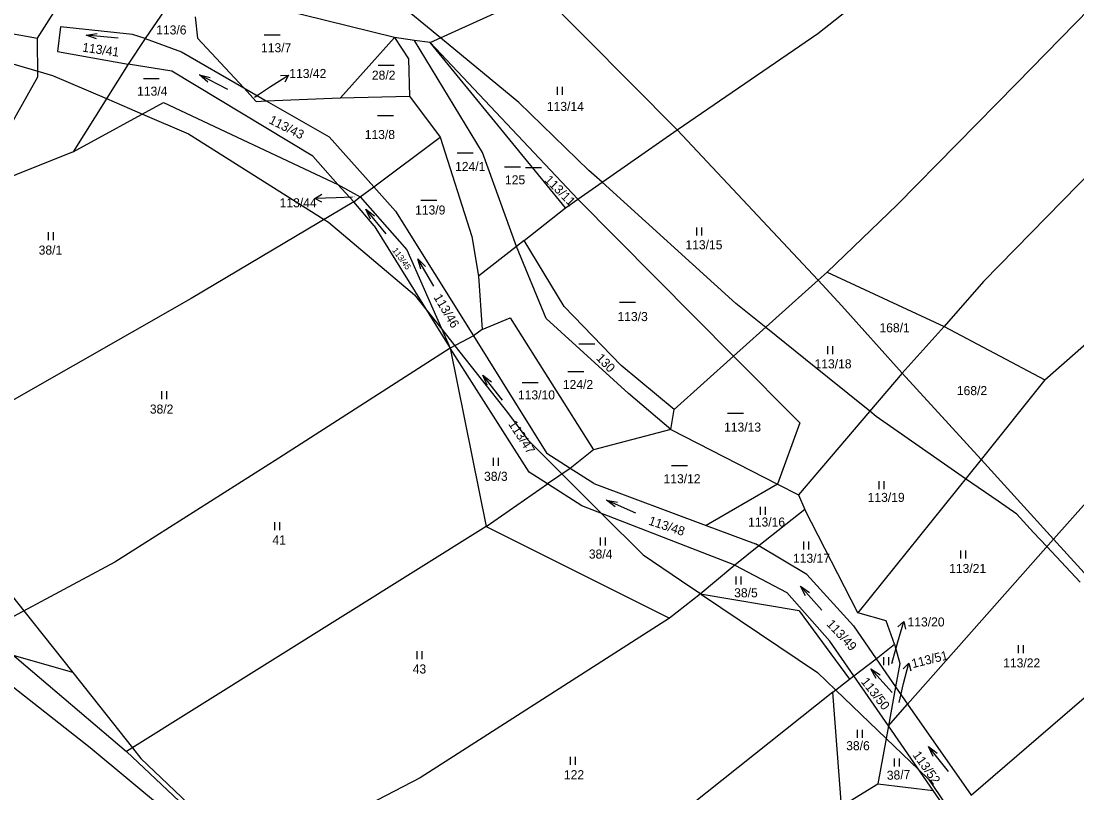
# Model space of a CAD drawing. Extents: x -749173 to -746119, y -1132678 to -1130338.
# Drawn here: x -747690.2 to -747491.9, y -1131005.9 to -1130860.8 of the extents above; entities that cross this region are included whole.
import ezdxf

# ---------------------------------------------------------------- set-up
doc = ezdxf.new("R2010")
doc.units = 0
for name, color, linetype in [('Vrstva 1', 7, 'Continuous'), ('Vrstva 16', 7, 'Continuous'), ('Vrstva 18', 7, 'Continuous'), ('Vrstva 25', 7, 'Continuous'), ('Vrstva 52', 7, 'Continuous'), ('Vrstva 6', 7, 'Continuous')]:
    doc.layers.add(name, color=color, linetype=linetype)

msp = doc.modelspace()

# ---------------------------------------------------------------- linework, layer by layer
at = {"layer": 'Vrstva 1'}
for points in [[(-747687.14, -1130864.03), (-747678.53, -1130850.34)], [(-747592.89, -1130855.02), (-747566.95, -1130881.22)], [(-747662, -1130856.84), (-747666.96, -1130864.06)], [(-747620.11, -1130863.87), (-747650.32, -1130856.36)], [(-747613.42, -1130864.85), (-747598.03, -1130857.85)], [(-747704.65, -1130860.86), (-747687.14, -1130864.03)], [(-747682.82, -1130861.87), (-747683.44, -1130866.5)], [(-747669.33, -1130863.29), (-747682.82, -1130861.87)], [(-747687.11, -1130871.26), (-747687.14, -1130864.03)], [(-747666.96, -1130864.06), (-747669.33, -1130863.29)], [(-747616.32, -1130864.44), (-747620.11, -1130863.87)], [(-747666.96, -1130864.06), (-747660.13, -1130866.55)], [(-747613.42, -1130864.85), (-747616.32, -1130864.44)], [(-747613.42, -1130864.85), (-747585.62, -1130894.26)], [(-747683.44, -1130866.5), (-747670.15, -1130868.87)], [(-747660.13, -1130866.55), (-747648.43, -1130873.34)], [(-747670.15, -1130868.87), (-747680.49, -1130885.34)], [(-747661.9, -1130870.18), (-747670.15, -1130868.87)], [(-747693.1, -1130881.99), (-747687.11, -1130871.26)], [(-747635.43, -1130886.18), (-747661.9, -1130870.18)], [(-747648.43, -1130873.34), (-747644.19, -1130875.8)], [(-747644.19, -1130875.8), (-747632.37, -1130882.58)], [(-747680.49, -1130885.34), (-747663.47, -1130876.12)], [(-747663.47, -1130876.12), (-747630.73, -1130891.53)], [(-747566.95, -1130881.22), (-747540.5, -1130909.52)], [(-747624, -1130891.96), (-747632.37, -1130882.58)], [(-747680.49, -1130885.34), (-747734.07, -1130906.85)], [(-747630.73, -1130891.53), (-747635.43, -1130886.18)], [(-747627.71, -1130894.75), (-747630.73, -1130891.53)], [(-747619.89, -1130896.55), (-747624, -1130891.96)], [(-747623.92, -1130899.27), (-747627.71, -1130894.75)], [(-747585.62, -1130894.26), (-747556.37, -1130923.79)], [(-747619.89, -1130896.55), (-747605.27, -1130919.98)], [(-747623.92, -1130899.27), (-747609.63, -1130922.29)], [(-747540.5, -1130909.52), (-747536.03, -1130914.31)], [(-747536.03, -1130914.31), (-747524.7, -1130926.96)], [(-747605.27, -1130919.98), (-747591.5, -1130942.05)], [(-747594.77, -1130945.6), (-747609.63, -1130922.29)], [(-747556.37, -1130923.79), (-747543.96, -1130936.32)], [(-747524.7, -1130926.96), (-747509.89, -1130943.21)], [(-747543.96, -1130936.32), (-747548.12, -1130947.84)], [(-747587.06, -1130944.87), (-747591.5, -1130942.05)], [(-747509.89, -1130943.21), (-747496.26, -1130958.17)], [(-747582.62, -1130947.7), (-747587.06, -1130944.87)], [(-747591.34, -1130947.8), (-747594.77, -1130945.6)], [(-747584.92, -1130951.93), (-747591.34, -1130947.8)], [(-747582.62, -1130947.7), (-747561.51, -1130955.61)], [(-747548.12, -1130947.84), (-747561.51, -1130955.61)], [(-747556.12, -1130963.07), (-747584.92, -1130951.93)], [(-747561.51, -1130955.61), (-747552.29, -1130959.07)], [(-747551.66, -1130959.44), (-747552.29, -1130959.07)], [(-747496.26, -1130958.17), (-747480.85, -1130975.08)], [(-747542.61, -1130964.81), (-747551.66, -1130959.44)], [(-747556.12, -1130963.07), (-747546.35, -1130968.19)], [(-747542.61, -1130964.81), (-747533.86, -1130974.48)], [(-747538.28, -1130977.32), (-747546.35, -1130968.19)], [(-747533.86, -1130974.48), (-747529.57, -1130980.67)], [(-747696.99, -1130975.53), (-747670.43, -1130998.05)], [(-747533.76, -1130983.87), (-747538.28, -1130977.32)], [(-747677.24, -1130997.39), (-747699.35, -1130980.06)], [(-747529.57, -1130980.67), (-747525.94, -1130985.9)], [(-747527.29, -1130993.25), (-747533.76, -1130983.87)], [(-747525.94, -1130985.9), (-747523.68, -1130989.16)], [(-747523.68, -1130989.16), (-747511.77, -1131006.31)], [(-747518.9, -1131005.41), (-747527.29, -1130993.25)], [(-747641.15, -1131027.46), (-747677.24, -1130997.39)], [(-747670.43, -1130998.05), (-747647.48, -1131019.78)], [(-747515.79, -1131009.83), (-747518.9, -1131005.41)]]:
    msp.add_lwpolyline(points, dxfattribs=at)
at = {"layer": 'Vrstva 16'}
for p, q in [((-747641.51, -1130871.02), (-747640.01, -1130870.94)), ((-747633.73, -1130894.84), (-747635.05, -1130894.14)), ((-747525.5, -1130974.67), (-747524.42, -1130973.62)), ((-747524.51, -1130982.53), (-747523.47, -1130981.45))]:
    msp.add_line(p, q, dxfattribs=at)
for points in [[(-747643.37, -1130873.12), (-747640.01, -1130870.94), (-747640.7, -1130872.28)], [(-747646.42, -1130875.1), (-747643.37, -1130873.12)], [(-747631.05, -1130894.01), (-747635.05, -1130894.14), (-747633.77, -1130893.34)], [(-747627.99, -1130893.91), (-747631.05, -1130894.01)], [(-747525.51, -1130977.47), (-747524.42, -1130973.62), (-747524.05, -1130975.08)], [(-747526.65, -1130981.51), (-747525.51, -1130977.47)], [(-747524.43, -1130985.33), (-747523.47, -1130981.45), (-747523.05, -1130982.89)], [(-747525.3, -1130988.86), (-747524.43, -1130985.33)]]:
    msp.add_lwpolyline(points, dxfattribs=at)
at = {"layer": 'Vrstva 25'}
for p, q in [((-747672.03, -1130864.03), (-747678.01, -1130863.43)), ((-747644.55, -1130863.36), (-747641.55, -1130863.36)), ((-747623.17, -1130869.11), (-747620.17, -1130869.11)), ((-747667.28, -1130871.61), (-747664.28, -1130871.61)), ((-747651.39, -1130873.64), (-747656.73, -1130870.92)), ((-747589.55, -1130873.13), (-747589.55, -1130874.63)), ((-747588.55, -1130874.63), (-747588.55, -1130873.13)), ((-747623.28, -1130878.56), (-747620.28, -1130878.56)), ((-747608.3, -1130885.57), (-747605.3, -1130885.57)), ((-747599.42, -1130888.17), (-747596.42, -1130888.17)), ((-747595.5, -1130888.31), (-747592.5, -1130888.31)), ((-747615.13, -1130894.45), (-747612.13, -1130894.45)), ((-747621.66, -1130900.78), (-747625.5, -1130896.16)), ((-747563.37, -1130899.61), (-747563.37, -1130901.11)), ((-747562.37, -1130901.11), (-747562.37, -1130899.61)), ((-747685.14, -1130900.49), (-747685.14, -1130901.99)), ((-747684.14, -1130901.99), (-747684.14, -1130900.49)), ((-747612.7, -1130910.65), (-747615.72, -1130905.47)), ((-747577.79, -1130913.63), (-747574.79, -1130913.63)), ((-747585.47, -1130921.44), (-747582.47, -1130921.44)), ((-747538.75, -1130921.87), (-747538.75, -1130923.37)), ((-747537.75, -1130923.37), (-747537.75, -1130921.87)), ((-747599.79, -1130932.06), (-747603.51, -1130927.36)), ((-747587.5, -1130926.66), (-747584.5, -1130926.66)), ((-747596.08, -1130928.75), (-747593.08, -1130928.75)), ((-747663.88, -1130930.37), (-747663.88, -1130931.87)), ((-747662.88, -1130931.87), (-747662.88, -1130930.37)), ((-747557.53, -1130934.52), (-747554.53, -1130934.52)), ((-747601.55, -1130942.89), (-747601.55, -1130944.39)), ((-747600.55, -1130944.39), (-747600.55, -1130942.89)), ((-747568.07, -1130944.3), (-747565.07, -1130944.3)), ((-747529.09, -1130947.28), (-747529.09, -1130948.78)), ((-747528.09, -1130948.78), (-747528.09, -1130947.28)), ((-747574.75, -1130953.28), (-747580.23, -1130950.84)), ((-747551.4, -1130952.09), (-747551.4, -1130953.59)), ((-747550.4, -1130953.59), (-747550.4, -1130952.09)), ((-747642.62, -1130954.98), (-747642.62, -1130956.48)), ((-747641.62, -1130956.48), (-747641.62, -1130954.98)), ((-747581.46, -1130957.86), (-747581.46, -1130959.36)), ((-747580.46, -1130959.36), (-747580.46, -1130957.86)), ((-747543.23, -1130958.6), (-747543.23, -1130960.1)), ((-747542.23, -1130960.1), (-747542.23, -1130958.6)), ((-747513.73, -1130960.33), (-747513.73, -1130961.83)), ((-747512.73, -1130961.83), (-747512.73, -1130960.33)), ((-747555.94, -1130965.2), (-747555.94, -1130966.7)), ((-747554.94, -1130966.7), (-747554.94, -1130965.2)), ((-747539.8, -1130971.5), (-747543.8, -1130967.02)), ((-747502.89, -1130978.08), (-747502.89, -1130979.58)), ((-747501.89, -1130979.58), (-747501.89, -1130978.08)), ((-747615.88, -1130979.22), (-747615.88, -1130980.72)), ((-747614.88, -1130980.72), (-747614.88, -1130979.22)), ((-747528.21, -1130980.35), (-747528.21, -1130981.85)), ((-747527.21, -1130981.85), (-747527.21, -1130980.35)), ((-747526.57, -1130987), (-747530.57, -1130982.52)), ((-747533.16, -1130994.01), (-747533.16, -1130995.51)), ((-747532.16, -1130995.51), (-747532.16, -1130994.01)), ((-747516, -1131001.84), (-747519.76, -1130997.16)), ((-747587.11, -1130999.09), (-747587.11, -1131000.59)), ((-747586.11, -1131000.59), (-747586.11, -1130999.09)), ((-747526.19, -1130999.39), (-747526.19, -1131000.89)), ((-747525.19, -1131000.89), (-747525.19, -1130999.39))]:
    msp.add_line(p, q, dxfattribs=at)
for points in [[(-747676.06, -1130864.13), (-747678.01, -1130863.43), (-747675.97, -1130863.13)], [(-747655.18, -1130872.27), (-747656.73, -1130870.92), (-747654.72, -1130871.38)], [(-747624.6, -1130898.02), (-747625.5, -1130896.16), (-747623.83, -1130897.38)], [(-747615.15, -1130907.45), (-747615.72, -1130905.47), (-747614.28, -1130906.94)], [(-747602.66, -1130929.24), (-747603.51, -1130927.36), (-747601.88, -1130928.62)], [(-747578.61, -1130952.11), (-747580.23, -1130950.84), (-747578.2, -1130951.2)], [(-747542.84, -1130968.85), (-747543.8, -1130967.02), (-747542.09, -1130968.18)], [(-747529.61, -1130984.35), (-747530.57, -1130982.52), (-747528.86, -1130983.68)], [(-747518.9, -1130999.03), (-747519.76, -1130997.16), (-747518.12, -1130998.41)]]:
    msp.add_lwpolyline(points, dxfattribs=at)
at = {"layer": 'Vrstva 52'}
for points in [[(-747756.37, -1130835.62), (-747756.6, -1130837.87), (-747756.78, -1130839.59), (-747757.5, -1130846.75), (-747757.45, -1130846.89), (-747756.2, -1130850.2), (-747752.37, -1130860.37), (-747749, -1130865.5), (-747743.06, -1130878.25), (-747734.56, -1130893.5), (-747731.9, -1130898.82), (-747728.92, -1130904.78), (-747726.87, -1130908.87), (-747725.19, -1130911.37), (-747724.75, -1130913.87), (-747720.5, -1130921.62), (-747715.81, -1130929.25), (-747709.44, -1130942), (-747709.4, -1130942.06), (-747701.81, -1130954.75), (-747697.12, -1130962.37), (-747689.74, -1130971.65), (-747680.5, -1130983.25)], [(-747491.25, -1130966.25), (-747497.5, -1130959.57), (-747500, -1130956.9), (-747503.19, -1130953.5), (-747506.68, -1130951.06), (-747512.78, -1130946.81), (-747529.56, -1130935.12), (-747530.8, -1130934.12), (-747542.84, -1130924.42), (-747550.35, -1130918.38), (-747555.94, -1130913.87), (-747581.1, -1130891.1), (-747583.56, -1130888.87), (-747596.75, -1130876.12), (-747611.45, -1130863.95), (-747620.18, -1130856.73)], [(-747693.31, -1130868.37), (-747687.11, -1130870.19), (-747684.37, -1130871), (-747674.23, -1130875.36), (-747669.87, -1130877.24), (-747667.46, -1130878.28), (-747658.81, -1130882), (-747633.33, -1130898.1), (-747632.5, -1130898.62), (-747616.31, -1130912.25), (-747614.2, -1130914.93), (-747611.2, -1130918.73), (-747608.76, -1130921.83), (-747598.87, -1130934.37), (-747595.06, -1130939.5), (-747588.61, -1130945.93), (-747581.12, -1130953.4), (-747573.37, -1130961.12), (-747566.16, -1130965.99), (-747562.55, -1130968.44), (-747562.38, -1130968.55), (-747540.62, -1130983.25), (-747537.21, -1130986.52), (-747527.72, -1130995.61), (-747521.64, -1131001.44), (-747519.75, -1131003.25), (-747515.47, -1131009.55)], [(-747680.5, -1130983.25), (-747691.67, -1130980.04), (-747701.37, -1130977.25), (-747706.65, -1130976.57), (-747717.66, -1130975.17), (-747720.94, -1130974.75), (-747726.93, -1130974.31), (-747727.75, -1130974.25), (-747742.78, -1130972.07), (-747751.25, -1130970.84), (-747767.28, -1130968.52), (-747778.94, -1130966.83), (-747784.65, -1130966.01), (-747786.44, -1130965.75), (-747797.15, -1130964.68), (-747802.66, -1130964.13), (-747805.51, -1130963.84), (-747806.65, -1130964.52), (-747807.18, -1130963.67)], [(-747680.5, -1130983.25), (-747669.34, -1130997.37), (-747667.75, -1130999.37), (-747657.56, -1131009.12), (-747643.99, -1131017.97), (-747632.06, -1131025.75), (-747617.56, -1131037.25), (-747615.5, -1131039.37), (-747604, -1131051.25), (-747603.65, -1131051.67), (-747597.62, -1131059), (-747596.31, -1131061.12), (-747595.1, -1131062.76), (-747594.19, -1131064), (-747594.01, -1131064.25), (-747585.25, -1131076.75), (-747577.22, -1131091.12), (-747569.73, -1131104.54)]]:
    msp.add_lwpolyline(points, dxfattribs=at)
at = {"layer": 'Vrstva 6'}
for points in [[(-747442.58, -1130810.47), (-747503.21, -1130872.55)], [(-747540.53, -1130863.15), (-747518.65, -1130845.8)], [(-747453.02, -1130852.06), (-747509.43, -1130909.76)], [(-747657.53, -1130859.98), (-747657.11, -1130864.01)], [(-747657.11, -1130864.01), (-747648.43, -1130873.34)], [(-747620.11, -1130863.87), (-747630.22, -1130875.23)], [(-747620.11, -1130863.87), (-747617.49, -1130867.91)], [(-747566.95, -1130881.22), (-747540.53, -1130863.15)], [(-747666.96, -1130864.06), (-747670.15, -1130868.87)], [(-747603.54, -1130885.52), (-747616.32, -1130864.44)], [(-747587.99, -1130895.92), (-747613.42, -1130864.85)], [(-747617.49, -1130867.91), (-747617.27, -1130874.92)], [(-747648.43, -1130873.34), (-747646.1, -1130875.88)], [(-747503.21, -1130872.55), (-747525.65, -1130895.32)], [(-747646.1, -1130875.88), (-747644.19, -1130875.8)], [(-747644.19, -1130875.8), (-747630.22, -1130875.23)], [(-747630.22, -1130875.23), (-747617.27, -1130874.92)], [(-747617.27, -1130874.92), (-747611.5, -1130882.62)], [(-747585.62, -1130894.26), (-747566.95, -1130881.22)], [(-747624, -1130891.96), (-747611.5, -1130882.62)], [(-747611.5, -1130882.62), (-747605.55, -1130901.3)], [(-747597.18, -1130903.17), (-747603.54, -1130885.52)], [(-747630.73, -1130891.53), (-747626.52, -1130893.83)], [(-747626.52, -1130893.83), (-747624, -1130891.96)], [(-747627.71, -1130894.75), (-747658.27, -1130912.95)], [(-747627.71, -1130894.75), (-747626.52, -1130893.83)], [(-747626.52, -1130893.83), (-747617.8, -1130903.81)], [(-747587.99, -1130895.92), (-747585.62, -1130894.26)], [(-747525.65, -1130895.32), (-747538.78, -1130907.97)], [(-747595.75, -1130902.05), (-747587.99, -1130895.92)], [(-747605.55, -1130901.3), (-747604.33, -1130908.77)], [(-747597.18, -1130903.17), (-747604.33, -1130908.77)], [(-747595.75, -1130902.05), (-747597.18, -1130903.17)], [(-747591.59, -1130916.72), (-747597.18, -1130903.17)], [(-747588.22, -1130914.45), (-747595.75, -1130902.05)], [(-747617.8, -1130903.81), (-747609.63, -1130922.29)], [(-747604.33, -1130908.77), (-747603.65, -1130918.79)], [(-747540.5, -1130909.52), (-747556.37, -1130923.79)], [(-747538.78, -1130907.97), (-747540.5, -1130909.52)], [(-747538.78, -1130907.97), (-747516.82, -1130918.2)], [(-747509.43, -1130909.76), (-747516.82, -1130918.2)], [(-747496.26, -1130958.17), (-747454.36, -1130911.13)], [(-747658.27, -1130912.95), (-747714.21, -1130944.8)], [(-747577.5, -1130925.53), (-747588.22, -1130914.45)], [(-747497.88, -1130928.23), (-747483.39, -1130915.42)], [(-747603.65, -1130918.79), (-747598.35, -1130916.55)], [(-747598.35, -1130916.55), (-747582.67, -1130941.38)], [(-747576.11, -1130930.77), (-747591.59, -1130916.72)], [(-747603.65, -1130918.79), (-747605.27, -1130919.98)], [(-747516.82, -1130918.2), (-747524.7, -1130926.96)], [(-747516.82, -1130918.2), (-747497.88, -1130928.23)], [(-747605.27, -1130919.98), (-747609.63, -1130922.29)], [(-747609.63, -1130922.29), (-747641.8, -1130942.93)], [(-747609.63, -1130922.29), (-747602.88, -1130955.82)], [(-747556.37, -1130923.79), (-747567.53, -1130933.83)], [(-747567.53, -1130933.83), (-747577.5, -1130925.53)], [(-747524.7, -1130926.96), (-747544.17, -1130949.82)], [(-747497.88, -1130928.23), (-747509.89, -1130943.21)], [(-747568.14, -1130937.53), (-747576.11, -1130930.77)], [(-747568.14, -1130937.53), (-747567.53, -1130933.83)], [(-747568.14, -1130937.53), (-747582.67, -1130941.38)], [(-747568.14, -1130937.53), (-747548.12, -1130947.84)], [(-747582.67, -1130941.38), (-747587.06, -1130944.87)], [(-747641.8, -1130942.93), (-747672.66, -1130962.51)], [(-747509.89, -1130943.21), (-747533.01, -1130972.03)], [(-747587.06, -1130944.87), (-747591.34, -1130947.8)], [(-747602.88, -1130955.82), (-747591.34, -1130947.8)], [(-747548.12, -1130947.84), (-747544.17, -1130949.82)], [(-747544.17, -1130949.82), (-747542.97, -1130952.61)], [(-747542.97, -1130952.61), (-747551.66, -1130959.44)], [(-747533.01, -1130972.03), (-747542.97, -1130952.61)], [(-747602.88, -1130955.82), (-747670.43, -1130998.05)], [(-747602.88, -1130955.82), (-747568.39, -1130973)], [(-747523.68, -1130989.16), (-747496.26, -1130958.17)], [(-747551.66, -1130959.44), (-747556.12, -1130963.07)], [(-747672.66, -1130962.51), (-747696.99, -1130975.53)], [(-747556.12, -1130963.07), (-747562.63, -1130968.51)], [(-747562.63, -1130968.51), (-747568.39, -1130973)], [(-747544.05, -1130971.62), (-747562.63, -1130968.51)], [(-747568.39, -1130973), (-747615.24, -1131003.06)], [(-747544.05, -1130971.62), (-747534.58, -1130984.5)], [(-747527.69, -1130973.54), (-747533.01, -1130972.03)], [(-747526.17, -1130977.92), (-747527.69, -1130973.54)], [(-747529.57, -1130980.67), (-747526.17, -1130977.92)], [(-747526.17, -1130977.92), (-747525.13, -1130981.52)], [(-747533.76, -1130983.87), (-747529.57, -1130980.67)], [(-747525.13, -1130981.52), (-747525.94, -1130985.9)], [(-747537.72, -1130986.92), (-747534.58, -1130984.5)], [(-747534.58, -1130984.5), (-747533.76, -1130983.87)], [(-747537.72, -1130986.92), (-747564.39, -1131008.14)], [(-747536.11, -1131008.38), (-747537.72, -1130986.92)], [(-747525.94, -1130985.9), (-747527.29, -1130993.25)], [(-747511.77, -1131006.31), (-747490.53, -1130988)], [(-747527.29, -1130993.25), (-747523.68, -1130989.16)], [(-747527.29, -1130993.25), (-747529.3, -1131004.16)], [(-747615.24, -1131003.06), (-747647.48, -1131019.78)], [(-747536.11, -1131008.38), (-747529.3, -1131004.16)], [(-747529.3, -1131004.16), (-747518.9, -1131005.41)]]:
    msp.add_lwpolyline(points, dxfattribs=at)

# ---------------------------------------------------------------- texts
at = {"layer": 'Vrstva 16'}
for s, p in [('113/42', (-747639.85, -1130871.49)), ('113/44', (-747641.67, -1130895.8)), ('113/20', (-747523.69, -1130974.58))]:
    msp.add_text(s, height=1.7, dxfattribs=at).set_placement(p)
msp.add_text('113/51', height=1.7, rotation=13.9617, dxfattribs=at).set_placement((-747522.71, -1130982.42))
at = {"layer": 'Vrstva 18'}
for s, height, p in [('113/6', 1.7, (-747664.86, -1130863.31)), ('113/7', 1.7, (-747645.17, -1130866.66)), ('28/2', 1.7, (-747624.34, -1130871.81)), ('113/4', 1.7, (-747668.45, -1130874.82)), ('113/42', 0.1, (-747646.42, -1130875.1)), ('113/14', 1.7, (-747591.46, -1130877.69)), ('113/8', 1.7, (-747625.68, -1130882.97)), ('124/1', 1.7, (-747608.71, -1130888.97)), ('125', 1.7, (-747599.33, -1130891.48)), ('113/44', 0.1, (-747627.99, -1130893.91)), ('113/9', 1.7, (-747616.22, -1130897.15)), ('38/1', 1.7, (-747686.95, -1130904.69)), ('113/15', 1.7, (-747565.43, -1130903.69)), ('113/3', 1.7, (-747578.19, -1130917.18)), ('168/1', 1.7, (-747528.97, -1130919.29)), ('113/18', 1.7, (-747541.17, -1130926.07)), ('124/2', 1.7, (-747588.46, -1130929.95)), ('168/2', 1.7, (-747514.43, -1130931.1)), ('113/10', 1.7, (-747596.89, -1130931.91)), ('38/2', 1.7, (-747666.06, -1130934.57)), ('113/13', 1.7, (-747558.17, -1130937.96)), ('38/3', 1.7, (-747603.26, -1130947.21)), ('113/12', 1.7, (-747569.54, -1130947.67)), ('113/19', 1.7, (-747531.19, -1130951.17)), ('113/16', 1.7, (-747553.66, -1130955.8)), ('41', 1.7, (-747643.03, -1130959.18)), ('38/4', 1.7, (-747583.58, -1130961.82)), ('113/17', 1.7, (-747545.22, -1130962.61)), ('113/21', 1.7, (-747515.88, -1130964.53)), ('38/5', 1.7, (-747556.27, -1130969.1)), ('113/22', 1.7, (-747505.72, -1130982.28)), ('43', 1.7, (-747616.67, -1130983.42)), ('113/20', 0.1, (-747526.65, -1130981.51)), ('113/51', 0.1, (-747525.3, -1130988.86)), ('38/6', 1.7, (-747535.22, -1130997.84)), ('122', 1.7, (-747588.26, -1131003.29))]:
    msp.add_text(s, height=height, dxfattribs=at).set_placement(p)
for s, height, rotation, p in [('113/41', 1.7, 351.9268, (-747678.83, -1130866.52)), ('113/43', 1.7, 333.2289, (-747643.84, -1130879.93)), ('113/11', 1.7, 315, (-747592.03, -1130890.79)), ('113/45', 1.14, 306.2188, (-747620.57, -1130903.9)), ('113/46', 1.7, 300.5933, (-747612.81, -1130912.69)), ('130', 1.7, 313.9191, (-747582.33, -1130924.25)), ('113/47', 1.7, 302.9885, (-747598.77, -1130936.53)), ('113/48', 1.7, 341.7461, (-747572.49, -1130955.41)), ('113/49', 1.7, 312.7741, (-747539.04, -1130974.22)), ('113/50', 1.7, 308.2901, (-747532.54, -1130985)), ('113/52', 1.7, 305.4171, (-747522.82, -1130998.74)), ('38/7', 1.7, 2.0479, (-747527.56, -1131003.41))]:
    msp.add_text(s, height=height, rotation=rotation, dxfattribs=at).set_placement(p)

doc.saveas('drawing.dxf')
